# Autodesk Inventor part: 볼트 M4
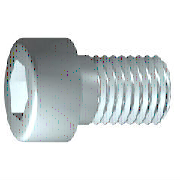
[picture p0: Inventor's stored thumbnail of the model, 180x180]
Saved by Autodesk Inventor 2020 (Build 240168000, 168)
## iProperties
Created: 2012-02
Part Number: 볼트 M4
Material: 알루미늄 6061
Description: 6각머리 태핑 나사
Document SubType Name: Modeling
Standard: KS B 1003
Designer: mduedu
Standards Organization: KS
Language: ko-KR
Size Designation: M 4 x 10
Categories: <MemberInstance><Categories><Category DisplayName="조임쇠" InternalName="e4da775c-781d-43d5-af7c-5136215cf5a6" Mnemonic="FSTN"><Category DisplayName="볼트" InternalN
Density: 2.7 g/cm^3
Mass: 0.699769 g
Surface Area: 3.0572 cm^2
Volume: 0.259174 cm^3
Appearance: 알루미늄 - 평지
IsCustomPart: 1
Author: mduedu
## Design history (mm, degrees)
sketch "스케치1"
  geometry: L1 (-1, 0)-(10, 0); L2 (10, 0)-(10, 2); L3 (10, 2)-(1.75, 2); L4 (1.75, 2)-(1.32, 2); L5 (1.32, 2)-(0, 2); L6 (0, 2)-(0, 3.5); L7 (0, 3.5)-(-4, 3.5); L8 (-4, 3.5)-(-4, 1.732); L9 (-4, 1.732)-(-2, 1.732); L10 (-2, 1.732)-(-1, 0); L11 (-6.8, 0)-(12.8, 0) reference; L12 (0, -0.7)-(0, 4.2) reference; L13 (1.75, 2)-(0, 2)
  constraints: 22 end point, 6 parallel, 2 collinear, 2 perpendicular, 1 horizontal, 1 point on line
  dimensions: "d1" = 8.25 distance from line of L3.end L2 (= GEL); "d2" = 0.42952 distance of L4.end L3.end (computed from GAL); "d3" = 4 distance between parallel lines of L8 L6 (= KOH); "d4" = 2 distance of L8.end L9.end (= INTI); "d5" = 60 deg angle of L10 L1; "d6" = 4 diameter of L3 L1 (= GD); "d7" = 4 diameter of L5 L1 (= BDM); "d8" = 3.4641 diameter of L9 L1 (= 1.1547 x SW); "d9" = 7 diameter of L7 L1 (= KOD); "d26" = 10 distance between parallel lines of L12 L2 (= NLG)
revolve "본체" sketch "스케치1" stored, may be unused: angle "d10" = 90 deg
sketch "스케치2"
  geometry: L1 (0, -4.9)-(0, 4.9) reference; L2 (-4.9, 0)-(4.9, 0) reference; L3 (1.732, 0)-(0.866, -1.5); L4 (0.866, -1.5)-(-0.866, -1.5); L5 (-0.866, -1.5)-(-1.732, 0); L6 (-1.732, 0)-(-0.866, 1.5); L7 (-0.866, 1.5)-(0.866, 1.5); L8 (0.866, 1.5)-(1.732, 0); 2 further points
  constraints: 12 end point, 1 coincident, 1 horizontal alignment, 1 point on line, 12 other
extrude "슬롯" join sketch "스케치2" stored distance "d11" = 10; taper "d12" = 0 deg
workplane "Work Plane1"
fillet "Fillet2" dims "d30" = 0.1 (= R)
body "Solid1"
fillet "모깎기1" dims "d17" = 0.4 (= RR)
feature "스레드" dims "d13" = 8.25 (= GEL), "d14" = 0
chamfer "모따기1" distance "d15" = 0.42941 (= -0.5 x SPD + 0.5 x GD); stored, may be unused: second distance "d16" = 0.42941 (= GUL), angle "d27" = 45 deg
other parameters: "GD" = 4 (= NND) [user parameter; used in 2 equation terms], "NLG" = 10 [user parameter; used in 1 equation term], "GEL" = 8.25 [user parameter; used in 2 equation terms], "KOD" = 7 [user parameter; used in 1 equation term], "KOH" = 4 [user parameter; used in 1 equation term], "INTI" = 2 [user parameter; used in 1 equation term], "GAL" = 0.42941 (= 0.61345 x PTC) [user parameter; used in 1 equation term], "GUL" = 0.42941 (= 0.61345 x PTC) [user parameter; used in 1 equation term], "BDM" = 4 (= NND) [user parameter; used in 1 equation term], "SW" = 3 [user parameter; used in 2 equation terms], "RR" = 0.4 [user parameter; used in 1 equation term], "SPD" = 3.14117 (= NND - 1.2269 x PTC) [user parameter; used in 1 equation term], "d19" = 0, "d28" = 0, "d29" = 0, "R" = 0.1 [user parameter; used in 1 equation term], "PHH" = 0.2 [user parameter], "GD1" = 3.14117 (= THREADDIA - 1.2269 x PTC) [user parameter], "THREADDIA" = 4 [user parameter; used in 1 equation term], "FAWI" = 45 deg [user parameter], "TPU" = 14.28571 (computed from PTC) [user parameter], "PTC" = 0.7 [user parameter; used in 5 equation terms], "NND" = 4 [user parameter; used in 3 equation terms], "TOA" = 30 deg [user parameter], "E0" = 3.465 (= 1.155 x SW) [user parameter]
